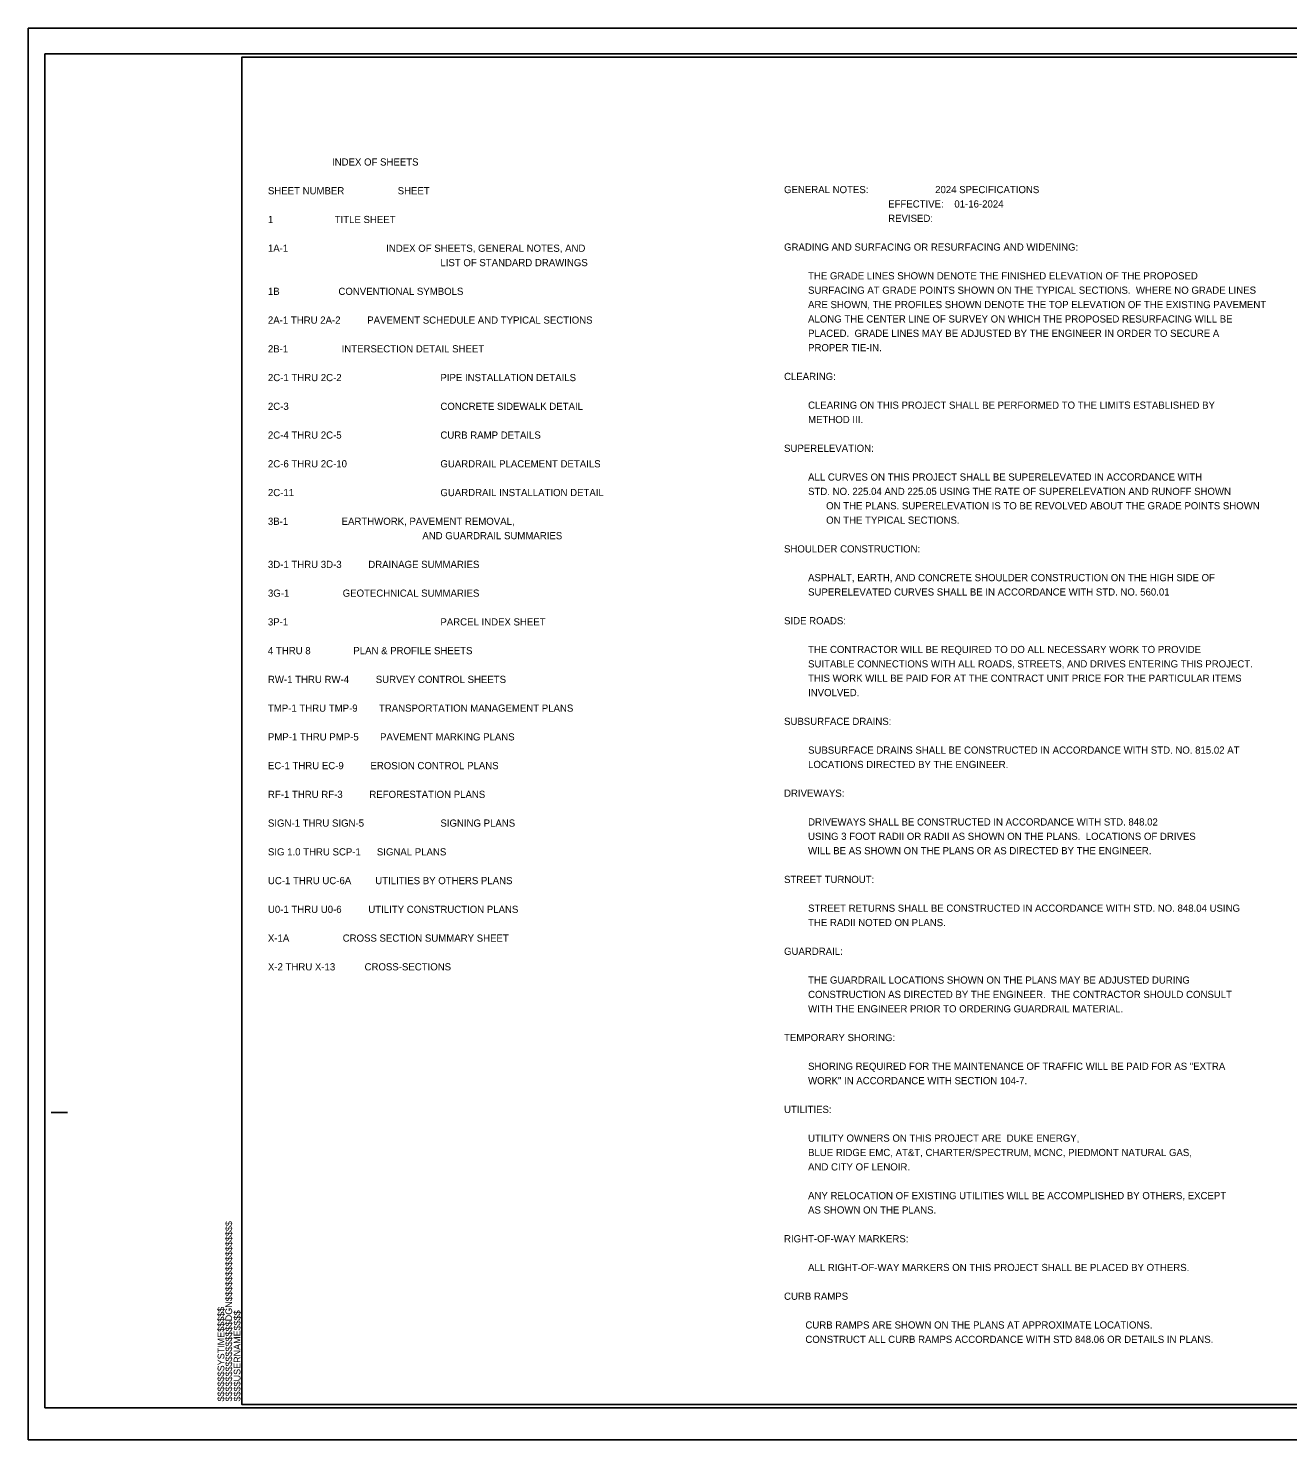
# Model space of a CAD drawing. Extents: x 573687 to 576329, y -53413 to -52265.
# Drawn here: x 573687 to 574668, y -53365 to -52265 of the extents above; entities that cross this region are included whole.
import ezdxf

# ---------------------------------------------------------------- set-up
doc = ezdxf.new("R2010")
doc.units = 0
for name, color, linetype in [('Sheet Cutting Line CELL', 7, 'Continuous'), ('Sheet Data Text CELL', 7, 'Continuous'), ('Sheet Plan CELL', 7, 'Continuous'), ('Sheet Plot Border Inside CELL', 7, 'Continuous'), ('Sheet Plot Border Outside CELL', 7, 'Continuous')]:
    doc.layers.add(name, color=color, linetype=linetype)

msp = doc.modelspace()

# ---------------------------------------------------------------- linework, layer by layer
at = {"layer": 'Sheet Cutting Line CELL'}
msp.add_line((575370.2, -52264.9), (573686.7, -52264.9), dxfattribs=at)
at = {"layer": 'Sheet Plan CELL'}
for p, q in [((573704.7, -53109.9), (573717.2, -53109.9)), ((573853.2, -53337.4), (573853.2, -53337.4))]:
    msp.add_line(p, q, dxfattribs=at)
msp.add_lwpolyline([(575353.2, -52287.4), (573853.2, -52287.4), (573853.2, -53337.4), (575353.2, -53337.4)], close=True, dxfattribs=at)
at = {"layer": 'Sheet Plot Border Inside CELL'}
msp.add_lwpolyline([(573699.7, -53339.9), (575365.7, -53339.9), (575365.7, -52284.9), (573699.7, -52284.9)], close=True, dxfattribs=at)
at = {"layer": 'Sheet Plot Border Outside CELL'}
msp.add_lwpolyline([(573686.7, -52264.9), (575386.7, -52264.9), (575386.7, -53364.9), (573686.7, -53364.9)], close=True, dxfattribs=at)

# ---------------------------------------------------------------- texts
at = {"layer": 'Sheet Data Text CELL'}
for s, p in [('                        INDEX OF SHEETS ', (573873.5, -52371.9)), ('SHEET NUMBER                    SHEET   ', (573873.5, -52394.3)), ('GENERAL NOTES:                         2024 SPECIFICATIONS', (574275.7, -52393.4)), ('                                       EFFECTIVE:    01-16-2024', (574275.7, -52404.6)), ('1                       TITLE SHEET', (573873.5, -52416.7)), ('                                       REVISED:      ', (574275.7, -52415.8)), ('1A-1 ', (573873.5, -52439.1)), ('            INDEX OF SHEETS, GENERAL NOTES, AND ', (573940.7, -52439.1)), ('GRADING AND SURFACING OR RESURFACING AND WIDENING:  ', (574275.7, -52438.2)), ('LIST OF STANDARD DRAWINGS', (574007.9, -52450.3)), ('         THE GRADE LINES SHOWN DENOTE THE FINISHED ELEVATION OF THE PROPOSED ', (574275.7, -52460.6)), ('1B                      CONVENTIONAL SYMBOLS ', (573873.5, -52472.7)), ('         SURFACING AT GRADE POINTS SHOWN ON THE TYPICAL SECTIONS.  WHERE NO GRADE LINES ', (574275.7, -52471.8)), ('         ARE SHOWN, THE PROFILES SHOWN DENOTE THE TOP ELEVATION OF THE EXISTING PAVEMENT ', (574275.7, -52483)), ('2A-1 THRU 2A-2          PAVEMENT SCHEDULE AND TYPICAL SECTIONS', (573873.5, -52495.1)), ('         ALONG THE CENTER LINE OF SURVEY ON WHICH THE PROPOSED RESURFACING WILL BE ', (574275.7, -52494.2)), ('         PLACED.  GRADE LINES MAY BE ADJUSTED BY THE ENGINEER IN ORDER TO SECURE A ', (574275.7, -52505.4)), ('2B-1                    INTERSECTION DETAIL SHEET ', (573873.5, -52517.5)), ('         PROPER TIE-IN.  ', (574275.7, -52516.6)), ('2C-1 THRU 2C-2   ', (573873.5, -52539.9)), ('PIPE INSTALLATION DETAILS', (574007.9, -52539.9)), ('CLEARING:  ', (574275.7, -52539)), ('2C-3', (573873.5, -52562.3)), ('CONCRETE SIDEWALK DETAIL', (574007.9, -52562.3)), ('         CLEARING ON THIS PROJECT SHALL BE PERFORMED TO THE LIMITS ESTABLISHED BY ', (574275.7, -52561.4)), ('         METHOD III.', (574275.7, -52572.6)), ('2C-4 THRU 2C-5      ', (573873.5, -52584.7)), ('CURB RAMP DETAILS', (574007.9, -52584.7)), ('SUPERELEVATION:  ', (574275.7, -52595)), ('2C-6 THRU 2C-10      ', (573873.5, -52607.1)), ('GUARDRAIL PLACEMENT DETAILS  ', (574007.9, -52607.1)), ('         ALL CURVES ON THIS PROJECT SHALL BE SUPERELEVATED IN ACCORDANCE WITH', (574275.7, -52617.4)), ('2C-11     ', (573873.5, -52629.5)), ('GUARDRAIL INSTALLATION DETAIL', (574007.9, -52629.5)), ('         STD. NO. 225.04 AND 225.05 USING THE RATE OF SUPERELEVATION AND RUNOFF SHOWN ', (574275.7, -52628.6)), ('     ON THE PLANS. SUPERELEVATION IS TO BE REVOLVED ABOUT THE GRADE POINTS SHOWN', (574298.1, -52639.8)), ('     ON THE TYPICAL SECTIONS.  ', (574298.1, -52651)), ('3B-1                    EARTHWORK, PAVEMENT REMOVAL, ', (573873.5, -52651.9)), ('    AND GUARDRAIL SUMMARIES ', (573985.5, -52663.1)), ('SHOULDER CONSTRUCTION:  ', (574275.7, -52673.4)), ('3D-1 THRU 3D-3          DRAINAGE SUMMARIES', (573873.5, -52685.5)), ('         ASPHALT, EARTH, AND CONCRETE SHOULDER CONSTRUCTION ON THE HIGH SIDE OF', (574275.7, -52695.8)), ('3G-1                    GEOTECHNICAL SUMMARIES ', (573873.5, -52707.9)), ('         SUPERELEVATED CURVES SHALL BE IN ACCORDANCE WITH STD. NO. 560.01', (574275.7, -52707)), ('3P-1', (573873.5, -52730.3)), ('PARCEL INDEX SHEET', (574007.9, -52730.3)), ('SIDE ROADS:  ', (574275.7, -52729.4)), ('4 THRU 8                PLAN & PROFILE SHEETS', (573873.5, -52752.7)), ('         THE CONTRACTOR WILL BE REQUIRED TO DO ALL NECESSARY WORK TO PROVIDE ', (574275.7, -52751.8)), ('         SUITABLE CONNECTIONS WITH ALL ROADS, STREETS, AND DRIVES ENTERING THIS PROJECT.  ', (574275.7, -52763)), ('RW-1 THRU RW-4          SURVEY CONTROL SHEETS', (573873.5, -52775.1)), ('         THIS WORK WILL BE PAID FOR AT THE CONTRACT UNIT PRICE FOR THE PARTICULAR ITEMS ', (574275.7, -52774.2)), ('         INVOLVED.    ', (574275.7, -52785.4)), ('TMP-1 THRU TMP-9        TRANSPORTATION MANAGEMENT PLANS', (573873.5, -52797.5)), ('SUBSURFACE DRAINS:', (574275.7, -52807.8)), ('PMP-1 THRU PMP-5        PAVEMENT MARKING PLANS', (573873.5, -52819.9)), ('         SUBSURFACE DRAINS SHALL BE CONSTRUCTED IN ACCORDANCE WITH STD. NO. 815.02 AT ', (574275.7, -52830.2)), ('EC-1 THRU EC-9          EROSION CONTROL PLANS', (573873.5, -52842.3)), ('         LOCATIONS DIRECTED BY THE ENGINEER.  ', (574275.7, -52841.4)), ('RF-1 THRU RF-3          REFORESTATION PLANS', (573873.5, -52864.7)), ('DRIVEWAYS:  ', (574275.7, -52863.8)), ('SIGN-1 THRU SIGN-5', (573873.5, -52887.1)), ('SIGNING PLANS', (574007.9, -52887.1)), ('         DRIVEWAYS SHALL BE CONSTRUCTED IN ACCORDANCE WITH STD. 848.02', (574275.7, -52886.2)), ('         USING 3 FOOT RADII OR RADII AS SHOWN ON THE PLANS.  LOCATIONS OF DRIVES', (574275.7, -52897.4)), ('SIG 1.0 THRU SCP-1      SIGNAL PLANS', (573873.5, -52909.5)), ('         WILL BE AS SHOWN ON THE PLANS OR AS DIRECTED BY THE ENGINEER.  ', (574275.7, -52908.6)), ('UC-1 THRU UC-6A         UTILITIES BY OTHERS PLANS', (573873.5, -52931.9)), ('STREET TURNOUT:  ', (574275.7, -52931)), ('U0-1 THRU U0-6          UTILITY CONSTRUCTION PLANS', (573873.5, -52954.3)), ('         STREET RETURNS SHALL BE CONSTRUCTED IN ACCORDANCE WITH STD. NO. 848.04 USING ', (574275.7, -52953.4)), ('         THE RADII NOTED ON PLANS.  ', (574275.7, -52964.6)), ('X-1A                    CROSS SECTION SUMMARY SHEET', (573873.5, -52976.7)), ('GUARDRAIL:  ', (574275.7, -52987)), ('X-2 THRU X-13           CROSS-SECTIONS', (573873.5, -52999.1)), ('         THE GUARDRAIL LOCATIONS SHOWN ON THE PLANS MAY BE ADJUSTED DURING ', (574275.7, -53009.4)), ('         CONSTRUCTION AS DIRECTED BY THE ENGINEER.  THE CONTRACTOR SHOULD CONSULT', (574275.7, -53020.6)), ('         WITH THE ENGINEER PRIOR TO ORDERING GUARDRAIL MATERIAL.', (574275.7, -53031.8)), ('TEMPORARY SHORING:  ', (574275.7, -53054.2)), ('         SHORING REQUIRED FOR THE MAINTENANCE OF TRAFFIC WILL BE PAID FOR AS "EXTRA ', (574275.7, -53076.6)), ('         WORK" IN ACCORDANCE WITH SECTION 104-7.  ', (574275.7, -53087.8)), ('UTILITIES:  ', (574275.7, -53110.2)), ('         UTILITY OWNERS ON THIS PROJECT ARE  DUKE ENERGY, ', (574275.7, -53132.6)), ('         BLUE RIDGE EMC, AT&T, CHARTER/SPECTRUM, MCNC, PIEDMONT NATURAL GAS,', (574275.7, -53143.8)), ('         AND CITY OF LENOIR.', (574275.7, -53155)), ('         ANY RELOCATION OF EXISTING UTILITIES WILL BE ACCOMPLISHED BY OTHERS, EXCEPT ', (574275.7, -53177.4)), ('         AS SHOWN ON THE PLANS.  ', (574275.7, -53188.6)), ('RIGHT-OF-WAY MARKERS:  ', (574275.7, -53211)), ('         ALL RIGHT-OF-WAY MARKERS ON THIS PROJECT SHALL BE PLACED BY OTHERS.  ', (574275.7, -53233.4)), ('CURB RAMPS', (574275.7, -53255.8)), ('        CURB RAMPS ARE SHOWN ON THE PLANS AT APPROXIMATE LOCATIONS.', (574275.7, -53278.2)), ('        CONSTRUCT ALL CURB RAMPS ACCORDANCE WITH STD 848.06 OR DETAILS IN PLANS.', (574275.7, -53289.4))]:
    msp.add_text(s, height=5.6, dxfattribs=at).set_placement(p)
at = {"layer": 'Sheet Plan CELL'}
for s, p in [('$$$$$$$$$$$$$$$$DGN$$$$$$$$$$$$$$$$', (573845.6, -53335)), ('$$$$$$SYSTIME$$$$$', (573839.5, -53335)), ('$$$$USERNAME$$$$', (573852.1, -53335))]:
    msp.add_text(s, height=5.25, rotation=90, dxfattribs=at).set_placement(p)

doc.saveas('drawing.dxf')
